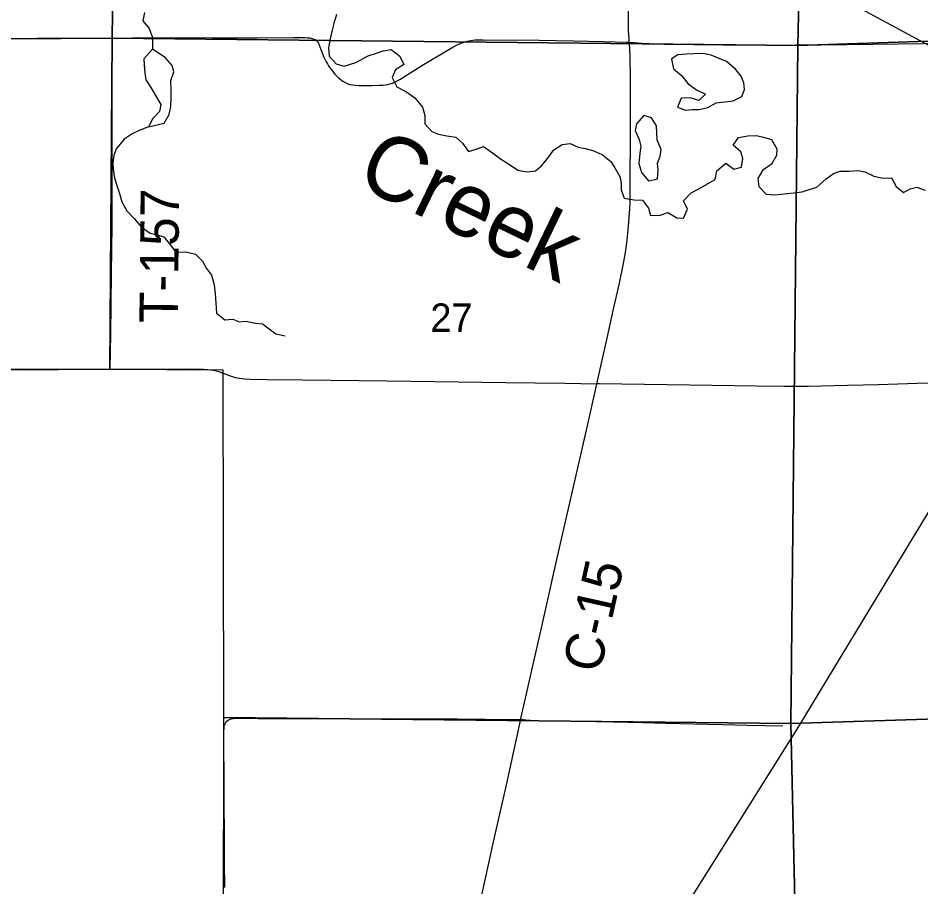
# Model space of a CAD drawing. Extents: x 0 to 34, y 0 to 22.
# Drawn here: x 5.173 to 5.839, y 18.123 to 18.765 of the extents above; entities that cross this region are included whole.
import ezdxf

# ---------------------------------------------------------------- set-up
doc = ezdxf.new("R2010")
doc.units = 0
for name, color, linetype in [('GM_X_Corporation', 7, 'Continuous'), ('GM_X_County_Road', 7, 'Continuous'), ('GM_X_County_Road_Text', 7, 'Continuous'), ('GM_X_Minor_Lake', 7, 'Continuous'), ('GM_X_Minor_River', 7, 'Continuous'), ('GM_X_Minor_River_Text', 7, 'Continuous'), ('GM_X_Rail_Line', 7, 'Continuous'), ('GM_X_Section_Text', 7, 'Continuous'), ('GM_X_Township_Road', 7, 'Continuous'), ('GM_X_Township_Road_Text', 7, 'Continuous'), ('SH_Text', 7, 'Continuous')]:
    doc.layers.add(name, color=color, linetype=linetype)

msp = doc.modelspace()

# ---------------------------------------------------------------- linework, layer by layer
at = {"layer": 'GM_X_Corporation'}
for points in [[(5.75962, 19.24856), (6.25957, 19.26329), (6.25155, 18.76101), (5.74855, 18.74422)], [(5.27672, 19.24181), (5.75962, 19.24856), (5.74855, 18.74422), (5.24266, 18.7496), (5.24725, 19.07984), (5.2474, 19.09955), (5.25754, 19.11327), (5.26142, 19.12014), (5.2659, 19.12909), (5.26978, 19.14013), (5.27366, 19.15027), (5.27813, 19.1634), (5.27962, 19.17175), (5.28141, 19.17981), (5.28171, 19.18966), (5.28201, 19.19711), (5.28112, 19.20517), (5.28042, 19.21447), (5.28022, 19.2171), (5.27903, 19.22337), (5.27724, 19.23322)], [(5.74855, 18.74422), (6.25155, 18.76101), (6.24542, 18.26006), (5.74338, 18.24402)], [(5.24266, 18.7496), (5.74855, 18.74422), (5.74338, 18.24402), (5.32507, 18.24835), (5.32477, 18.50478), (5.24099, 18.50517)], [(5.74338, 18.24402), (6.24542, 18.26006), (6.23511, 17.75666), (6.21312, 17.75585), (5.73364, 17.74138), (5.73061, 17.74103), (5.74922, 17.99349)], [(5.32507, 18.24835), (5.74338, 18.24402), (5.74922, 17.99349), (5.73061, 17.74103), (5.26362, 17.74328), (5.23463, 17.74294), (5.2393, 18.08245), (5.32486, 18.08313)]]:
    msp.add_lwpolyline(points, close=True, dxfattribs=at)
for points in [[(5.24725, 19.07984), (5.24266, 18.7496), (4.74554, 18.74756), (4.73633, 18.74761), (4.74607, 19.20756)], [(4.74554, 18.74756), (5.24266, 18.7496), (5.24099, 18.50517), (4.97533, 18.50359)]]:
    msp.add_lwpolyline(points, dxfattribs=at)
at = {"layer": 'GM_X_County_Road'}
for points in [[(5.62429, 18.74663), (5.62409, 18.74914), (5.62371, 18.75533), (5.6237, 18.7615), (5.62382, 18.7848)], [(5.60038, 18.49471), (5.60203, 18.50231), (5.60795, 18.52836), (5.61247, 18.5487), (5.61702, 18.56902), (5.61997, 18.58334), (5.62149, 18.5916), (5.62241, 18.5984), (5.6234, 18.6083), (5.62462, 18.62376), (5.62489, 18.6281), (5.62497, 18.63146), (5.62499, 18.63462), (5.62503, 18.64114), (5.62503, 18.64672), (5.62498, 18.6517), (5.62501, 18.65852), (5.62517, 18.66287), (5.62512, 18.66443), (5.62515, 18.66908), (5.62524, 18.67809), (5.62527, 18.68463), (5.6252, 18.69238), (5.62525, 18.69704), (5.62523, 18.70015), (5.62516, 18.70325), (5.62512, 18.70759), (5.62508, 18.71224), (5.62508, 18.71595), (5.62513, 18.72123), (5.62494, 18.7352), (5.62462, 18.74234), (5.62429, 18.74663)], [(5.54426, 18.24708), (5.54439, 18.24766), (5.54928, 18.26917), (5.55242, 18.28344), (5.55846, 18.31011), (5.56462, 18.33741), (5.56895, 18.3565), (5.5871, 18.43589), (5.59262, 18.46046), (5.59913, 18.48894), (5.60038, 18.49471)], [(5.89335, 18.49658), (5.8834, 18.49615), (5.8686, 18.49582), (5.8368, 18.49489), (5.80821, 18.49398), (5.78521, 18.49334), (5.75661, 18.49259), (5.73856, 18.49265), (5.71804, 18.49298), (5.6854, 18.49343), (5.65216, 18.49388), (5.60205, 18.49468), (5.60038, 18.49471)], [(5.42914, 17.742), (5.42925, 17.74387), (5.42941, 17.74575), (5.4304, 17.75147), (5.43511, 17.77271), (5.44277, 17.80794), (5.45104, 17.84462), (5.46035, 17.88394), (5.46714, 17.91268), (5.47448, 17.9432), (5.48368, 17.98063), (5.48615, 17.99091), (5.48968, 18.00636), (5.49271, 18.01938), (5.50034, 18.05207), (5.50747, 18.08264), (5.5134, 18.10807), (5.51624, 18.12082), (5.52421, 18.15662), (5.53401, 18.19965), (5.54426, 18.24708)]]:
    msp.add_lwpolyline(points, dxfattribs=at)
at = {"layer": 'GM_X_Minor_Lake'}
for points in [[(5.27243, 18.74148), (5.26613, 18.73449), (5.26682, 18.72424), (5.26755, 18.71892), (5.2713, 18.7132), (5.27467, 18.70749), (5.2788, 18.70063), (5.27763, 18.6957), (5.27267, 18.69042), (5.2696, 18.68436)], [(5.2696, 18.68436), (5.28117, 18.68695), (5.28481, 18.69338), (5.28598, 18.69926), (5.28621, 18.70571), (5.28625, 18.7116), (5.28611, 18.71843), (5.28823, 18.72487), (5.28712, 18.72962), (5.28186, 18.73535), (5.27243, 18.74148)], [(5.69469, 18.70275), (5.70105, 18.70342), (5.70731, 18.70661), (5.70923, 18.71172), (5.70888, 18.71665), (5.70683, 18.72159), (5.7027, 18.72692), (5.69611, 18.73246), (5.6895, 18.73515), (5.6846, 18.73726), (5.67855, 18.73843), (5.67193, 18.73809), (5.66644, 18.73793), (5.6602, 18.7374), (5.65545, 18.73439)], [(5.65545, 18.73439), (5.65692, 18.72718), (5.66275, 18.72222), (5.66764, 18.71612), (5.67385, 18.71154), (5.68046, 18.70847), (5.6757, 18.70375), (5.66928, 18.70569), (5.66247, 18.70535), (5.65997, 18.69872), (5.66582, 18.69661), (5.67074, 18.69696), (5.67585, 18.69712), (5.68229, 18.6986), (5.68836, 18.70198), (5.69469, 18.70275)], [(5.64306, 18.64546), (5.64509, 18.64591), (5.64569, 18.65236), (5.64516, 18.65748), (5.64708, 18.66259), (5.64786, 18.66751), (5.64488, 18.67454), (5.64472, 18.67985), (5.64437, 18.68497), (5.64081, 18.69087), (5.63515, 18.69261), (5.62963, 18.68657)], [(5.62963, 18.68657), (5.62865, 18.68146), (5.63164, 18.67499), (5.63275, 18.67006), (5.63196, 18.66476), (5.63134, 18.65718), (5.63339, 18.65053), (5.63846, 18.64443), (5.64306, 18.64546)]]:
    msp.add_lwpolyline(points, dxfattribs=at)
at = {"layer": 'GM_X_Minor_River'}
for points in [[(5.26673, 18.76865), (5.26536, 18.7624), (5.27006, 18.75686), (5.2723, 18.75097), (5.27246, 18.74622), (5.27243, 18.74148), (5.26613, 18.73449), (5.26629, 18.72956), (5.26682, 18.72424), (5.26755, 18.71892), (5.2713, 18.7132), (5.27467, 18.70749), (5.2788, 18.70063), (5.27763, 18.6957), (5.27267, 18.69042), (5.2696, 18.68436), (5.26276, 18.68156), (5.25763, 18.67912), (5.25174, 18.67517), (5.24601, 18.66837), (5.24408, 18.66326), (5.24329, 18.65776), (5.24364, 18.65301), (5.24455, 18.64674), (5.2464, 18.64028), (5.24826, 18.63514), (5.24992, 18.62887), (5.25348, 18.6224), (5.25894, 18.61667), (5.2642, 18.61057), (5.2708, 18.60578), (5.27572, 18.60462), (5.28082, 18.60307), (5.28571, 18.59697), (5.28984, 18.59182), (5.29704, 18.59196), (5.30422, 18.59021), (5.3095, 18.58525), (5.31249, 18.57973), (5.31606, 18.57477), (5.31809, 18.56774), (5.31881, 18.56109), (5.31933, 18.55444), (5.31966, 18.54666), (5.32588, 18.54188), (5.33176, 18.54241), (5.33667, 18.54049), (5.34141, 18.54084), (5.34859, 18.53947), (5.35371, 18.53887), (5.35861, 18.53523), (5.36351, 18.53141), (5.37032, 18.53004)], [(5.40821, 18.76725), (5.40627, 18.76062), (5.4051, 18.75569), (5.40373, 18.74924), (5.40237, 18.74261), (5.4029, 18.73653), (5.40816, 18.73081), (5.41402, 18.72906), (5.42257, 18.73167)], [(5.42257, 18.73167), (5.43168, 18.73659), (5.43774, 18.73864), (5.44267, 18.74032), (5.44873, 18.74142), (5.45513, 18.73646), (5.45793, 18.73037), (5.45186, 18.72624), (5.44936, 18.72056), (5.45273, 18.71391), (5.45933, 18.71027), (5.46611, 18.70568), (5.47175, 18.69883), (5.47341, 18.69275), (5.47356, 18.68649), (5.47864, 18.68078), (5.48354, 18.67885), (5.48978, 18.67768), (5.49639, 18.6767), (5.50129, 18.67212), (5.50579, 18.66603), (5.51053, 18.66752), (5.51678, 18.66976), (5.52338, 18.66517), (5.52921, 18.66078), (5.536, 18.65657), (5.54203, 18.65237), (5.54883, 18.651), (5.55508, 18.65172), (5.55983, 18.65568), (5.56402, 18.66096), (5.5686, 18.66738), (5.57487, 18.67114), (5.58073, 18.67187), (5.58658, 18.66937), (5.59168, 18.6682), (5.59811, 18.66665), (5.60452, 18.66358), (5.61073, 18.65881), (5.61373, 18.65405), (5.61729, 18.64759), (5.6182, 18.64265), (5.61836, 18.63772), (5.62041, 18.63164), (5.62778, 18.63047), (5.63402, 18.63024), (5.63852, 18.62434), (5.64001, 18.61883), (5.6472, 18.61898), (5.65269, 18.62104), (5.65948, 18.61721), (5.6644, 18.61699), (5.66727, 18.62361), (5.66428, 18.62969), (5.66999, 18.63554), (5.67512, 18.63835), (5.68765, 18.64549), (5.68901, 18.65192), (5.69547, 18.65739), (5.70131, 18.65299), (5.707, 18.65448), (5.70798, 18.66092), (5.7065, 18.66586), (5.70104, 18.67082), (5.70486, 18.67629), (5.71186, 18.67758), (5.71811, 18.67792), (5.7234, 18.67676), (5.72925, 18.67483), (5.73318, 18.66798), (5.73296, 18.66305), (5.72933, 18.65682), (5.72268, 18.65212), (5.71924, 18.64626), (5.71977, 18.64019), (5.72522, 18.63447), (5.73146, 18.63406), (5.73866, 18.63477), (5.74566, 18.63568), (5.75191, 18.63641), (5.75703, 18.63809), (5.76271, 18.63976), (5.76956, 18.64579), (5.77507, 18.64974), (5.78, 18.65161), (5.78643, 18.65157), (5.79305, 18.6521), (5.79796, 18.65113), (5.80475, 18.64787), (5.81156, 18.6465), (5.8178, 18.64666), (5.82117, 18.64019), (5.82663, 18.6358), (5.83156, 18.63862), (5.83649, 18.63973), (5.84253, 18.63761)]]:
    msp.add_lwpolyline(points, dxfattribs=at)
at = {"layer": 'GM_X_Rail_Line'}
msp.add_lwpolyline([(4.83086, 16.81428), (4.95348, 17.00356), (5.121, 17.25544), (5.31678, 17.55326), (5.45252, 17.7592), (5.58679, 17.98275), (5.74825, 18.23979), (5.90418, 18.49744), (6.02127, 18.68264), (6.13663, 18.87252), (6.2288, 19.01731), (6.34315, 19.20099), (6.38785, 19.27035), (6.55501, 19.53303), (6.71382, 19.79395), (6.76349, 19.87076), (6.84474, 20.00352), (6.94083, 20.16003), (7.03262, 20.3087), (7.17305, 20.5257), (7.19919, 20.56539)], dxfattribs=at)
at = {"layer": 'GM_X_Township_Road'}
for points in [[(4.95621, 18.74793), (4.95859, 18.74821), (4.96214, 18.74858), (4.96585, 18.74881), (4.9979, 18.74899), (5.0395, 18.74922), (5.06716, 18.74926), (5.11534, 18.7492), (5.16289, 18.74932), (5.20485, 18.74941), (5.24294, 18.74978)], [(5.24124, 18.50556), (5.2418, 18.53128), (5.2423, 18.576), (5.24267, 18.61171), (5.24277, 18.6443), (5.24275, 18.67659), (5.2428, 18.73187), (5.24294, 18.74919), (5.24294, 18.74978)], [(5.24294, 18.74978), (5.2578, 18.74993), (5.29197, 18.75028), (5.31682, 18.74993), (5.35004, 18.74996), (5.37644, 18.75014), (5.38484, 18.7501), (5.38687, 18.75001), (5.38859, 18.74987), (5.38947, 18.74972), (5.39041, 18.74945), (5.39154, 18.74901), (5.39245, 18.7486), (5.39339, 18.74794), (5.39427, 18.74701), (5.39489, 18.74602), (5.39553, 18.74463), (5.39605, 18.74329), (5.39676, 18.74125), (5.39768, 18.73879), (5.39872, 18.7362), (5.39993, 18.73369), (5.40068, 18.73221), (5.4016, 18.73071), (5.40241, 18.72938), (5.40364, 18.72759), (5.40532, 18.72535), (5.40706, 18.72317), (5.40944, 18.72071), (5.41068, 18.71968), (5.41186, 18.71876), (5.41298, 18.71803), (5.41396, 18.71743), (5.4156, 18.71656), (5.41668, 18.71606), (5.41804, 18.71561), (5.42004, 18.71519), (5.42215, 18.71499), (5.42498, 18.71475), (5.42839, 18.71483), (5.43458, 18.71489), (5.43959, 18.71503), (5.44246, 18.71514), (5.44446, 18.7153), (5.44609, 18.71557), (5.44782, 18.71591), (5.44962, 18.71652), (5.45139, 18.7173), (5.45351, 18.71835), (5.45513, 18.71922), (5.46197, 18.72353), (5.47249, 18.73017), (5.48738, 18.73919), (5.49356, 18.74276), (5.49823, 18.74518), (5.50164, 18.74661), (5.50458, 18.74751), (5.50729, 18.74805), (5.51036, 18.74839), (5.51629, 18.74852), (5.55791, 18.74818), (5.58308, 18.74763), (5.60561, 18.74714), (5.62224, 18.74677), (5.62429, 18.74663)], [(5.62429, 18.74663), (5.6278, 18.7464), (5.63336, 18.74594), (5.65039, 18.7453), (5.69344, 18.74483), (5.72486, 18.74459), (5.74762, 18.74478), (5.76562, 18.7447), (5.80372, 18.74527), (5.82231, 18.74551), (5.85984, 18.74612), (5.87879, 18.74679), (5.89491, 18.74726), (5.92096, 18.7474), (5.93818, 18.74763), (5.94151, 18.74772)], [(4.9963, 18.50513), (4.99872, 18.50539), (5.00316, 18.50563), (5.01559, 18.50565), (5.04853, 18.50567), (5.07463, 18.50556), (5.12621, 18.50533), (5.1576, 18.50546), (5.17439, 18.50558), (5.19614, 18.50553), (5.24124, 18.50556)], [(5.24124, 18.50556), (5.25362, 18.50556), (5.27942, 18.5055), (5.29589, 18.50561), (5.31017, 18.50547), (5.31324, 18.50529), (5.31527, 18.50506), (5.31749, 18.50468), (5.32136, 18.5037), (5.32473, 18.50251), (5.32864, 18.50104), (5.33057, 18.50029), (5.33369, 18.49939), (5.33682, 18.49873), (5.34053, 18.49831), (5.34459, 18.49807), (5.35703, 18.49795), (5.38313, 18.49747), (5.44558, 18.49673), (5.53291, 18.49558), (5.57672, 18.49501), (5.60038, 18.49471)], [(5.32585, 18.12288), (5.32575, 18.14277), (5.32546, 18.20493), (5.32528, 18.22669), (5.32514, 18.23573), (5.32526, 18.23837), (5.32535, 18.24035), (5.32551, 18.24166), (5.32576, 18.24277), (5.32609, 18.2438), (5.32658, 18.24471), (5.32744, 18.24573), (5.32839, 18.24647), (5.32925, 18.24693), (5.33016, 18.2473), (5.3311, 18.24759), (5.33225, 18.24779), (5.33527, 18.24782), (5.35053, 18.24768), (5.38721, 18.24752), (5.44596, 18.24769), (5.49755, 18.24742), (5.53858, 18.24701), (5.54273, 18.24706), (5.54426, 18.24708)], [(5.54426, 18.24708), (5.54791, 18.24682), (5.55433, 18.24632), (5.57552, 18.24586), (5.61252, 18.24526), (5.63455, 18.24469)], [(5.63455, 18.24469), (5.65106, 18.24426), (5.69334, 18.24322), (5.71106, 18.24285), (5.73749, 18.24232)]]:
    msp.add_lwpolyline(points, dxfattribs=at)
at = {"layer": 'SH_Text'}
msp.add_lwpolyline([(9.29702, 16.88204), (2.59655, 20.49713), (9.29702, 17.63625)], close=True, dxfattribs=at)

# ---------------------------------------------------------------- texts
at = {"layer": 'GM_X_County_Road_Text'}
msp.add_text('C-15', height=0.028409, rotation=77.43565, dxfattribs=at).set_placement((5.60261, 18.28035))
at = {"layer": 'GM_X_Minor_River_Text'}
msp.add_text('Creek', height=0.047366, rotation=334.19981, dxfattribs=at).set_placement((5.42119, 18.64208))
at = {"layer": 'GM_X_Section_Text'}
msp.add_text('27', height=0.020928, rotation=0.00001, dxfattribs=at).set_placement((5.47756, 18.533))
at = {"layer": 'GM_X_Township_Road_Text'}
msp.add_text('T-157', height=0.028409, rotation=89.43834, dxfattribs=at).set_placement((5.29124, 18.53929))

doc.saveas('drawing.dxf')
